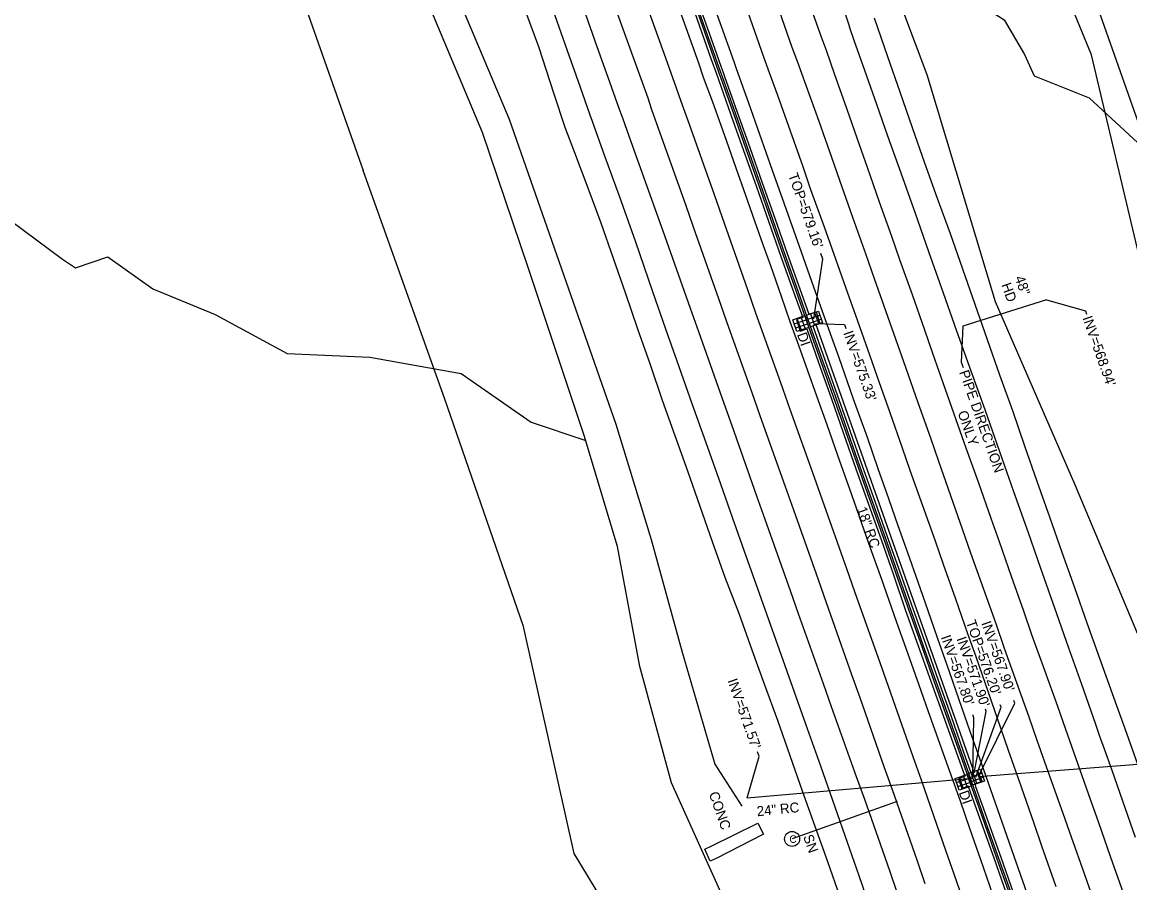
# Model space of a CAD drawing. Extents: x 2004847 to 2009016, y 1134161 to 1140101.
# Drawn here: x 2005737 to 2006180, y 1136539.1 to 1136883.1 of the extents above; entities that cross this region are included whole.
import ezdxf

# ---------------------------------------------------------------- set-up
doc = ezdxf.new("R2010")
doc.units = 0
for name, color, linetype in [('RD_EX_BldgApp', 7, 'Continuous'), ('RD_EX_Conc', 7, 'Continuous'), ('RD_EX_DR_Inlet', 7, 'Continuous'), ('RD_EX_DR_Inlet_txCode', 7, 'Continuous'), ('RD_EX_DR_Pipe', 7, 'Continuous'), ('RD_EX_DR_Pipe_txCode', 7, 'Continuous'), ('RD_EX_Fence_Other', 7, 'Continuous'), ('RD_EX_H2O', 7, 'Continuous'), ('RD_EX_Pavement_Markings', 7, 'Continuous'), ('RD_EX_Road', 7, 'Continuous'), ('RD_EX_VEG', 7, 'Continuous'), ('RD_Sketch3', 7, 'Continuous')]:
    doc.layers.add(name, color=color, linetype=linetype)

msp = doc.modelspace()

# ---------------------------------------------------------------- linework, layer by layer
at = {"layer": 'RD_EX_BldgApp'}
msp.add_line((2006086.98, 1136571.69), (2006044.94, 1136556.66), dxfattribs=at)
msp.add_circle((2006044.94, 1136556.66), 3, dxfattribs=at)
at = {"layer": 'RD_EX_Conc'}
for points in [[(2006007.3, 1136886.49), (2006013.51, 1136868.96), (2006015.67, 1136862.89)], [(2006007.95, 1136886.72), (2006014.16, 1136869.19), (2006016.34, 1136863.12)], [(2006016.34, 1136863.12), (2006017.1, 1136860.99), (2006022.11, 1136846.82), (2006027.09, 1136832.69), (2006032.1, 1136818.53), (2006037.11, 1136804.4), (2006042.08, 1136790.23), (2006047.09, 1136776.11), (2006052.06, 1136761.96), (2006057.08, 1136747.79), (2006062.1, 1136733.72), (2006067.06, 1136719.52), (2006072.04, 1136705.43), (2006077.05, 1136691.29), (2006082.11, 1136677.12), (2006087.08, 1136662.99), (2006092.42, 1136647.93), (2006097.41, 1136633.78), (2006102.42, 1136619.66), (2006107.44, 1136605.55), (2006112.48, 1136591.38), (2006117.46, 1136577.26), (2006122.46, 1136563.12), (2006127.45, 1136548.98), (2006132.48, 1136534.83)], [(2006015.67, 1136862.89), (2006016.43, 1136860.75), (2006021.44, 1136846.58), (2006026.43, 1136832.46), (2006031.43, 1136818.29), (2006036.44, 1136804.17), (2006041.41, 1136789.99), (2006046.41, 1136775.87), (2006051.4, 1136761.73), (2006056.38, 1136747.54), (2006061.42, 1136733.48), (2006066.42, 1136719.29), (2006071.36, 1136705.2), (2006076.37, 1136691.05), (2006081.43, 1136676.88), (2006086.42, 1136662.75), (2006091.78, 1136647.71), (2006096.77, 1136633.55), (2006101.75, 1136619.43), (2006106.78, 1136605.32), (2006111.84, 1136591.15), (2006116.8, 1136577.03), (2006121.82, 1136562.9), (2006126.82, 1136548.76), (2006131.84, 1136534.6)], [(2006031.24, 1136563.01), (2006033.54, 1136558.63), (2006014.52, 1136548.85), (2006012.21, 1136547.76), (2006010, 1136552.54), (2006012.88, 1136553.92), (2006031.24, 1136563.01)]]:
    msp.add_lwpolyline(points, dxfattribs=at)
at = {"layer": 'RD_EX_DR_Inlet'}
for p, q in [((2006051.27, 1136764.4), (2006056, 1136766.02)), ((2006052.33, 1136766.56), (2006053.95, 1136761.83)), ((2006053.94, 1136767.11), (2006055.56, 1136762.38)), ((2006045.82, 1136762.58), (2006050.55, 1136764.2)), ((2006046.38, 1136760.97), (2006051.1, 1136762.59)), ((2006046.88, 1136764.74), (2006048.5, 1136760.01)), ((2006048.49, 1136765.29), (2006050.11, 1136760.56)), ((2006051.83, 1136762.79), (2006056.56, 1136764.41)), ((2006118.74, 1136583.99), (2006120.36, 1136579.26)), ((2006110.68, 1136579.25), (2006115.41, 1136580.87)), ((2006111.74, 1136581.41), (2006113.36, 1136576.68)), ((2006113.35, 1136581.96), (2006114.97, 1136577.23)), ((2006116.07, 1136581.28), (2006120.8, 1136582.9)), ((2006116.62, 1136579.67), (2006121.35, 1136581.29)), ((2006117.13, 1136583.44), (2006118.75, 1136578.71)), ((2006111.24, 1136577.64), (2006115.97, 1136579.27))]:
    msp.add_line(p, q, dxfattribs=at)
for points in [[(2006046.89, 1136759.46), (2006045.27, 1136764.19), (2006050, 1136765.81), (2006051.62, 1136761.08)], [(2006052.35, 1136761.28), (2006050.72, 1136766.01), (2006055.45, 1136767.63), (2006057.07, 1136762.9)], [(2006117.14, 1136578.16), (2006115.52, 1136582.89), (2006120.25, 1136584.51), (2006121.87, 1136579.78)], [(2006111.76, 1136576.13), (2006110.13, 1136580.86), (2006114.86, 1136582.48), (2006116.48, 1136577.75)]]:
    msp.add_lwpolyline(points, close=True, dxfattribs=at)
at = {"layer": 'RD_EX_DR_Inlet_txCode'}
for points in [[(2006053.68, 1136764.51), (2006057.21, 1136788.45), (2006056.43, 1136790.65)], [(2006146.61, 1136772.12), (2006162.25, 1136767.77), (2006162.73, 1136766.42)], [(2006054.34, 1136762.66), (2006065.84, 1136762.23), (2006066.38, 1136760.72)], [(2006113.27, 1136761.61), (2006112.59, 1136747.24), (2006113.35, 1136745.07)], [(2006119.44, 1136581.64), (2006133.98, 1136610.91), (2006133.59, 1136611.99)], [(2006117.22, 1136580.93), (2006117.65, 1136605.07), (2006117.22, 1136606.27)], [(2006117.68, 1136583.02), (2006122.6, 1136607.63), (2006122.26, 1136608.59)], [(2006118.38, 1136581.29), (2006128.51, 1136609.38), (2006128.17, 1136610.32)], [(2006027.02, 1136573.08), (2006031.74, 1136589.67), (2006031.08, 1136591.52)]]:
    msp.add_lwpolyline(points, dxfattribs=at)
at = {"layer": 'RD_EX_DR_Pipe'}
for p, q in [((2006146.61, 1136772.12), (2006113.27, 1136761.61)), ((2006054.34, 1136762.66), (2006117.68, 1136583.02)), ((2006119.44, 1136581.64), (2006216.19, 1136589.1)), ((2006027.02, 1136573.08), (2006117.22, 1136580.93))]:
    msp.add_line(p, q, dxfattribs=at)
at = {"layer": 'RD_EX_Fence_Other'}
for points in [[(2006288.09, 1136544.58), (2006263.66, 1136615.63), (2006139.34, 1136967.96), (2006112.64, 1137043.07), (2006085.14, 1137118.91), (2006043.88, 1137235.25)], [(2005728.21, 1137230.79), (2005760.44, 1137139.08), (2005796.83, 1137035.67), (2005834.26, 1136935.09), (2005873.43, 1136823.78)], [(2006150.07, 1136043.34), (2006115.42, 1136139.93), (2006088.15, 1136218.09), (2006055.25, 1136311.48), (2006039.49, 1136357.1), (2006011.97, 1136432.75), (2005987.61, 1136501.5), (2005957.81, 1136550.91), (2005937.54, 1136641.63), (2005905.9, 1136732.88), (2005873.43, 1136823.78)]]:
    msp.add_lwpolyline(points, dxfattribs=at)
at = {"layer": 'RD_EX_H2O'}
msp.add_line((2005890.91, 1136941.31), (2005931.83, 1136844.29), dxfattribs=at)
for points in [[(2006112.75, 1136895.16), (2006129.71, 1136884.09), (2006137.9, 1136870.17), (2006141.69, 1136861.69), (2006163.76, 1136852.86), (2006190.28, 1136828.31), (2006196.59, 1136825.58), (2006201.05, 1136821.34), (2006205.27, 1136803.37), (2006204.48, 1136793.17), (2006204.25, 1136788.49), (2006204.86, 1136785.27), (2006219.54, 1136760.55), (2006230.66, 1136720.9)], [(2005601.87, 1136857.12), (2005648.58, 1136838.79), (2005694.69, 1136815.74), (2005732.31, 1136803.89), (2005753.19, 1136788.44), (2005758.39, 1136784.92), (2005771.25, 1136789.37), (2005789.24, 1136776.48), (2005814.15, 1136766.21), (2005843, 1136750.65), (2005876.07, 1136749.26)], [(2005931.83, 1136844.29), (2005974.38, 1136722.42), (2005988.63, 1136676.28), (2006001.03, 1136631.25), (2006014.08, 1136586.56), (2006024.85, 1136569.76)], [(2005876.07, 1136749.26), (2005912.53, 1136742.74), (2005940.55, 1136723.3), (2005962.09, 1136716.06)]]:
    msp.add_lwpolyline(points, dxfattribs=at)
at = {"layer": 'RD_EX_Pavement_Markings'}
for points in [[(2005835.74, 1137463.95), (2005849.99, 1137423.41), (2005864.31, 1137382.86), (2005875.05, 1137352.62), (2005889.45, 1137312.13), (2005903.79, 1137271.58), (2005914.78, 1137240.52), (2005929.22, 1137200.01), (2005943.64, 1137159.42), (2005954.6, 1137128.67), (2005968.92, 1137088.12), (2005983.37, 1137047.61), (2005994.06, 1137017.35), (2006008.29, 1136976.82), (2006022.62, 1136936.24), (2006033.58, 1136905.38), (2006044.8, 1136873.16)], [(2005848.16, 1137465.29), (2005862.54, 1137424.75), (2005873.26, 1137394.52), (2005887.52, 1137353.9), (2005901.86, 1137313.37), (2005912.8, 1137282.58), (2005927.2, 1137242.01), (2005941.56, 1137201.48), (2005952.55, 1137170.5), (2005966.97, 1137129.93), (2005981.38, 1137089.36), (2005992.2, 1137058.91), (2006006.54, 1137018.29), (2006020.9, 1136977.7), (2006031.81, 1136946.87), (2006046.21, 1136906.41), (2006056.57, 1136877.31)], [(2005825.14, 1137456.53), (2005839.37, 1137416.27), (2005850.1, 1137385.98), (2005864.5, 1137345.52), (2005878.93, 1137305.04), (2005893.4, 1137264.58), (2005904.08, 1137234.38), (2005918.39, 1137193.9), (2005932.63, 1137153.59), (2005943.36, 1137123.21), (2005957.73, 1137082.68), (2005972.14, 1137042.14), (2005982.82, 1137011.92), (2005997.23, 1136971.41), (2006011.61, 1136930.93), (2006022.67, 1136900.11), (2006033.56, 1136869.2)], [(2005788.73, 1137449.51), (2005803, 1137409.01), (2005817.4, 1137368.41), (2005828.16, 1137338.06), (2005842.73, 1137297.51), (2005857.07, 1137256.98), (2005871.02, 1137217), (2005881.73, 1137186.76), (2005896.21, 1137146.35), (2005910.61, 1137105.91), (2005921.22, 1137075.91), (2005935.53, 1137035.34), (2005949.65, 1136994.87), (2005963.61, 1136954.72), (2005974.36, 1136924.56), (2005988.85, 1136884.03), (2005994.3, 1136868.9), (2005998.63, 1136856.88)], [(2005778, 1137442.79), (2005792.39, 1137402.39), (2005803.4, 1137371.72), (2005817.89, 1137331.26), (2005832.25, 1137290.71), (2005846.44, 1137250.45), (2005857.1, 1137220.18), (2005871.38, 1137179.56), (2005885.58, 1137139.16), (2005896.39, 1137108.89), (2005910.75, 1137068.36), (2005925.12, 1137028.01), (2005939.05, 1136988.07), (2005949.65, 1136958.07), (2005963.92, 1136917.61), (2005978.44, 1136877.06), (2005982.82, 1136864.95), (2005987.2, 1136852.84)], [(2005766.92, 1137438.17), (2005781.39, 1137397.9), (2005805.91, 1137329.14), (2005820.24, 1137288.64), (2005834.58, 1137248.13), (2005845.47, 1137217.44), (2005859.69, 1137176.75), (2005873.98, 1137136.26), (2005888.4, 1137095.83), (2005898.99, 1137065.59), (2005913.39, 1137025.13), (2005927.49, 1136984.67), (2005938.3, 1136954.56), (2005952.56, 1136914.1), (2005966.89, 1136873.36), (2005971.3, 1136861.07), (2005975.7, 1136848.79)], [(2005997.41, 1136895.07), (2006002.48, 1136880.99), (2006007.46, 1136866.83), (2006009.42, 1136861.19)], [(2006011.51, 1136895.68), (2006016.59, 1136881.5), (2006021.64, 1136867.42), (2006022.49, 1136865.05)], [(2005949.93, 1136886.14), (2005955.01, 1136871.74), (2005960.01, 1136857.47), (2005964.1, 1136846.06)], [(2006066.22, 1136886.08), (2006067.85, 1136881.29)], [(2006182.24, 1136557.26), (2006177.23, 1136571.8), (2006172.89, 1136584.01), (2006169.86, 1136592.56), (2006167.88, 1136598.05), (2006166.21, 1136602.83), (2006160.74, 1136618.39), (2006155.49, 1136633.27), (2006149.94, 1136648.95), (2006144.22, 1136665.2), (2006139.41, 1136678.97), (2006133.63, 1136695.43), (2006127.94, 1136711.45), (2006122.09, 1136728.21), (2006116.54, 1136743.66), (2006110.82, 1136759.64), (2006105.47, 1136774.82), (2006099.62, 1136791.31), (2006094.24, 1136806.59), (2006088.52, 1136822.82), (2006083.27, 1136837.56), (2006078.83, 1136850.21), (2006073.99, 1136863.81), (2006069.79, 1136875.82), (2006067.85, 1136881.29)], [(2006056.57, 1136877.31), (2006058.49, 1136871.88), (2006061.8, 1136862.53), (2006066.78, 1136848.4), (2006071.76, 1136834.27), (2006074.92, 1136825.1), (2006079.8, 1136811.32), (2006084.68, 1136797.55), (2006087.93, 1136788.28), (2006092.91, 1136774.23), (2006097.89, 1136760.19), (2006101.1, 1136750.87), (2006106.17, 1136736.48), (2006111.24, 1136722.1), (2006114.45, 1136713), (2006119.41, 1136698.95), (2006124.38, 1136684.91), (2006127.7, 1136675.55), (2006132.58, 1136661.68), (2006137.45, 1136647.81), (2006140.72, 1136638.41), (2006145.86, 1136624.06), (2006151.01, 1136609.72), (2006154.2, 1136600.56), (2006159.19, 1136586.56), (2006164.18, 1136572.56), (2006167.3, 1136563.62), (2006172.29, 1136549.4), (2006177.28, 1136535.18)], [(2006044.8, 1136873.16), (2006047.01, 1136867.47), (2006050.44, 1136857.88), (2006055.57, 1136843.53), (2006060.7, 1136829.17), (2006063.86, 1136819.99), (2006069.13, 1136805.12), (2006074.4, 1136790.25), (2006077.73, 1136780.72), (2006082.38, 1136767.48), (2006087.02, 1136754.24), (2006090.25, 1136745.19), (2006095.25, 1136731.11), (2006100.26, 1136717.02), (2006103.44, 1136707.64), (2006108.22, 1136693.96), (2006113.01, 1136680.27), (2006116.31, 1136671), (2006121.33, 1136656.88), (2006126.34, 1136642.76), (2006129.74, 1136632.93), (2006134.65, 1136619.2), (2006139.57, 1136605.47), (2006142.83, 1136596.15), (2006148.03, 1136581.54), (2006153.23, 1136566.92), (2006156.54, 1136557.48), (2006161.69, 1136542.91), (2006166.84, 1136528.35)], [(2006033.56, 1136869.2), (2006035.81, 1136863.06), (2006039.05, 1136853.95), (2006044.14, 1136839.67), (2006049.22, 1136825.4), (2006052.35, 1136816.28), (2006057.71, 1136801.3), (2006063.08, 1136786.32), (2006066.23, 1136777.25), (2006071.08, 1136763.7), (2006075.92, 1136750.14), (2006078.96, 1136741.35), (2006083.97, 1136727.16), (2006088.98, 1136712.98), (2006092.08, 1136704.09), (2006097.11, 1136689.92), (2006102.15, 1136675.76), (2006105.34, 1136666.43), (2006110.24, 1136652.61), (2006115.14, 1136638.79), (2006118.37, 1136629.57), (2006123.31, 1136615.32), (2006128.25, 1136601.07), (2006131.39, 1136592.11), (2006136.5, 1136577.55), (2006141.6, 1136562.99), (2006144.73, 1136553.93), (2006150.43, 1136537.67)], [(2006022.49, 1136865.05), (2006024.62, 1136858.95), (2006027.48, 1136850.9), (2006031.92, 1136838.31), (2006036.96, 1136823.94), (2006041.74, 1136810.48), (2006047.73, 1136793.59), (2006052.74, 1136779.55), (2006058.26, 1136763.93), (2006063.6, 1136749.13), (2006069.39, 1136732.63), (2006074.91, 1136717.19), (2006079.25, 1136704.67), (2006083.42, 1136692.72), (2006087.22, 1136681.88), (2006091.02, 1136671.21), (2006095.19, 1136659.43), (2006099.19, 1136647.99), (2006102.99, 1136637.15), (2006107.77, 1136623.56), (2006111.67, 1136612.35), (2006116.01, 1136599.76), (2006120.62, 1136586.67), (2006122.47, 1136581.81), (2006134.46, 1136547.45), (2006172.52, 1136438.91)], [(2006009.42, 1136861.19), (2006013.06, 1136851.26), (2006016.39, 1136841.9), (2006019.48, 1136833.22), (2006022.44, 1136824.84), (2006026.24, 1136814.03), (2006029.91, 1136803.67), (2006033.24, 1136794.31), (2006036.3, 1136785.8), (2006040.54, 1136773.61), (2006044.07, 1136763.52), (2006047.47, 1136753.99), (2006051.1, 1136743.86), (2006054.73, 1136733.76), (2006058.84, 1136722.32), (2006063.14, 1136710.07), (2006068.66, 1136694.32), (2006072.73, 1136682.81), (2006076.16, 1136672.98), (2006080.63, 1136660.46), (2006086.69, 1136643.3), (2006090.42, 1136632.93), (2006095.67, 1136618.26), (2006099.27, 1136607.96), (2006102.02, 1136600.12), (2006107.84, 1136583.72), (2006112.08, 1136571.84), (2006115.92, 1136561.01), (2006120.32, 1136548.39), (2006125.13, 1136534.55)], [(2005998.63, 1136856.88), (2006000.46, 1136851.59), (2006003.81, 1136842.32), (2006013.77, 1136814.19), (2006016.83, 1136805.38), (2006027.14, 1136776.26), (2006030.36, 1136766.99), (2006040.28, 1136739.06), (2006044.04, 1136728.39), (2006053.72, 1136701.3), (2006057, 1136692.14), (2006066.72, 1136664.79), (2006069.94, 1136655.55), (2006080.07, 1136627.22), (2006083.38, 1136617.66), (2006093.24, 1136589.62), (2006096.49, 1136580.33), (2006106.43, 1136551.81), (2006109.64, 1136542.66), (2006119.64, 1136513.92)], [(2005987.2, 1136852.84), (2005988.73, 1136848.24), (2005992.09, 1136838.92), (2006002.32, 1136810.27), (2006005.39, 1136801.26), (2006015.51, 1136772.67), (2006018.64, 1136763.52), (2006028.81, 1136735.08), (2006032.04, 1136725.84), (2006042.13, 1136697.53), (2006045.43, 1136688.25), (2006055.31, 1136660.32), (2006058.52, 1136651.18), (2006068.72, 1136622.41), (2006071.98, 1136613.25), (2006081.68, 1136585.56), (2006084.94, 1136576.44), (2006094.82, 1136548.31), (2006098.06, 1136538.91)], [(2005964.1, 1136846.06), (2005965.01, 1136843.5), (2005969.92, 1136829.67), (2005975.74, 1136813.65), (2005982.27, 1136795.34), (2005989.16, 1136775.51), (2005994.31, 1136760.5), (2005999.62, 1136745.53), (2006004.87, 1136730.72), (2006010.42, 1136715.13), (2006016.27, 1136698.61), (2006021.12, 1136684.84), (2006027.04, 1136667.95), (2006032.59, 1136652.64), (2006038.27, 1136636.55), (2006044.29, 1136619.65), (2006050.31, 1136602.62), (2006056.3, 1136585.83), (2006061.98, 1136569.5), (2006066.89, 1136555.44), (2006071.6, 1136542.04), (2006076.82, 1136527)], [(2005975.7, 1136848.79), (2005977.22, 1136844.53), (2005980.45, 1136835.47), (2005990.77, 1136806.83), (2005993.94, 1136797.79), (2006004.21, 1136768.76), (2006007.54, 1136759.44), (2006017.59, 1136730.89), (2006020.78, 1136721.87), (2006030.72, 1136693.83), (2006033.98, 1136684.51), (2006044.13, 1136655.98), (2006047.34, 1136646.83), (2006057.39, 1136618.76), (2006060.6, 1136609.64), (2006070.6, 1136581.65), (2006073.83, 1136572.58), (2006083.86, 1136543.99), (2006087.01, 1136534.95)]]:
    msp.add_lwpolyline(points, dxfattribs=at)
at = {"layer": 'RD_EX_Road'}
msp.add_line((2006119.11, 1136584.03), (2006116.4, 1136583.13), dxfattribs=at)
for points in [[(2006005.79, 1136895.69), (2006012.46, 1136876.83), (2006016.44, 1136865.55), (2006017.19, 1136863.42)], [(2005936.53, 1136892.13), (2005943.57, 1136873.44), (2005949.66, 1136854.41), (2005954.01, 1136841.14)], [(2006006.02, 1136886.82), (2006012.49, 1136868.6), (2006014.64, 1136862.52)], [(2006077.77, 1136884.79), (2006083.11, 1136869.35), (2006088.07, 1136855.26), (2006092.9, 1136841), (2006097.92, 1136826.92), (2006102.9, 1136812.74), (2006108.08, 1136798.66), (2006113.07, 1136784.54), (2006117.99, 1136770.34), (2006123, 1136756.26), (2006127.9, 1136742.1), (2006133.02, 1136727.91), (2006137.89, 1136713.78), (2006142.85, 1136699.62), (2006147.81, 1136685.44), (2006152.82, 1136671.28), (2006157.87, 1136657.18), (2006162.79, 1136643.03), (2006167.86, 1136628.9), (2006172.94, 1136614.78), (2006177.98, 1136600.74), (2006183.04, 1136586.57)], [(2006017.19, 1136863.42), (2006017.94, 1136861.35), (2006022.94, 1136847.2), (2006027.97, 1136833.07), (2006033, 1136818.93), (2006038.02, 1136804.79), (2006043, 1136790.63), (2006048.02, 1136776.52), (2006051.56, 1136766.4)], [(2006014.64, 1136862.52), (2006015.46, 1136860.2), (2006020.48, 1136846.02), (2006025.47, 1136831.86), (2006030.54, 1136817.74), (2006035.55, 1136803.62), (2006040.48, 1136789.48), (2006045.48, 1136775.29), (2006049.16, 1136765.14)], [(2005954.01, 1136841.14), (2005957.93, 1136831.05), (2005963.21, 1136816.92), (2005968.38, 1136802.91), (2005973.34, 1136788.84), (2005978.27, 1136774.68), (2005983.04, 1136760.51), (2005988.2, 1136746.3), (2005993, 1136732.1), (2005998.07, 1136717.96), (2006003.04, 1136703.83), (2006008.03, 1136689.71), (2006012.97, 1136675.56), (2006018, 1136661.31), (2006023.77, 1136646.48), (2006028.77, 1136632.31), (2006033.96, 1136618.23), (2006039.15, 1136604.19), (2006044.08, 1136590), (2006048.91, 1136575.88), (2006054.06, 1136561.77), (2006059.15, 1136547.64), (2006063.98, 1136533.49)], [(2006051.56, 1136766.4), (2006054.5, 1136767.38), (2006056.08, 1136762.73), (2006053.19, 1136761.76)], [(2006049.16, 1136765.14), (2006046.64, 1136764.24), (2006048.16, 1136759.63), (2006050.82, 1136760.48)], [(2006053.19, 1136761.76), (2006058.01, 1136748.19), (2006063.02, 1136734.11), (2006068, 1136719.93), (2006072.96, 1136705.84), (2006077.96, 1136691.68), (2006082.99, 1136677.51), (2006088, 1136663.39), (2006093.34, 1136648.33), (2006098.37, 1136634.19), (2006103.35, 1136620.06), (2006108.37, 1136605.94), (2006113.36, 1136591.77), (2006116.4, 1136583.13), (2006117.95, 1136578.72)], [(2006050.82, 1136760.48), (2006055.53, 1136747.07), (2006060.52, 1136732.93), (2006065.53, 1136718.76), (2006070.47, 1136704.59), (2006075.48, 1136690.47), (2006080.49, 1136676.31), (2006085.49, 1136662.21), (2006090.29, 1136647.97), (2006095.38, 1136633.89), (2006100.47, 1136619.74), (2006105.51, 1136605.63), (2006110.55, 1136591.52), (2006114.03, 1136581.75)], [(2006117.95, 1136578.72), (2006120.88, 1136579.74), (2006119.11, 1136584.03)], [(2006114.03, 1136581.75), (2006111.46, 1136580.71), (2006112.83, 1136576.81), (2006115.39, 1136577.85)], [(2006115.39, 1136577.85), (2006115.54, 1136577.38), (2006120.52, 1136563.22), (2006125.58, 1136549.07), (2006130.6, 1136534.99), (2006135.61, 1136520.77), (2006140.62, 1136506.67), (2006145.63, 1136492.55), (2006150.53, 1136478.4), (2006155.62, 1136464.29), (2006160.66, 1136450.15), (2006165.63, 1136436.02), (2006170.61, 1136421.87), (2006170.87, 1136421.15)], [(2006117.95, 1136578.72), (2006118.33, 1136577.63), (2006123.3, 1136563.48), (2006128.35, 1136549.35), (2006133.36, 1136535.21), (2006138.37, 1136521.07), (2006143.36, 1136506.93), (2006148.41, 1136492.81), (2006153.45, 1136478.68), (2006158.59, 1136464.59), (2006163.42, 1136450.39), (2006168.46, 1136436.23), (2006173.24, 1136422.52)]]:
    msp.add_lwpolyline(points, dxfattribs=at)
at = {"layer": 'RD_EX_VEG'}
for points in [[(2006280.68, 1136541.58), (2006256.14, 1136612.63), (2006212.27, 1136710.57), (2006184.24, 1136787.39), (2006164.61, 1136870.02), (2006126.52, 1136962.8), (2006100.79, 1137039.92), (2006066.88, 1137123.34), (2006027.09, 1137230.77), (2006008.37, 1137303.96), (2005999.5, 1137331.93)], [(2005921.12, 1136839.02), (2005879.84, 1136937.44), (2005840.96, 1137039.96), (2005810.28, 1137148.31), (2005779.11, 1137247.96)], [(2006061.81, 1137035.33), (2006055.47, 1136986.65), (2006066.5, 1136947.96), (2006098.85, 1136862.24), (2006126.13, 1136771.44), (2006157.91, 1136698.56), (2006202.97, 1136591.32), (2006221.46, 1136521.07)], [(2005961.75, 1136717.89), (2005939.41, 1136785.12), (2005921.12, 1136839.02)], [(2006039.1, 1136535.19), (2006016.14, 1136535.95), (2005996.66, 1136579.1), (2005983.98, 1136625.63), (2005975.17, 1136673.57), (2005961.75, 1136717.89)]]:
    msp.add_lwpolyline(points, dxfattribs=at)

# ---------------------------------------------------------------- texts
at = {"layer": 'RD_EX_BldgApp'}
msp.add_text('C', height=3, dxfattribs=at).set_placement((2006043.86, 1136555.1))
at = {"layer": 'RD_EX_DR_Inlet_txCode'}
for s, p in [("TOP=579.16'", (2006043.29, 1136822.04)), ("INV=568.94'", (2006160.98, 1136764.89)), ('DI', (2006046.84, 1136758.31)), ("INV=575.33'", (2006065.34, 1136758.95)), ('PIPE DIRECTION', (2006111.71, 1136743.25)), ('ONLY', (2006111.07, 1136727.05)), ("TOP=576.20'", (2006114.41, 1136643.39)), ("INV=567.90'", (2006120.51, 1136642.92)), ("INV=567.80'", (2006104.37, 1136637.33)), ("INV=571.90'", (2006110.63, 1136636.69)), ("INV=571.57'", (2006019.06, 1136619.96)), ('DI', (2006111.55, 1136575.21))]:
    msp.add_text(s, height=4, rotation=289.4494, dxfattribs=at).set_placement(p)
at = {"layer": 'RD_EX_DR_Pipe_txCode'}
for s, rotation, p in [('HD', 289.4494, (2006128.54, 1136778.14)), ('48"', 289.4494, (2006133.91, 1136780.97)), ('18" RC', 289.4494, (2006070.77, 1136688.59)), ('24" RC', 5.7387, (2006030.99, 1136565.7))]:
    msp.add_text(s, height=4, rotation=rotation, dxfattribs=at).set_placement(p)
at = {"layer": 'RD_Sketch3'}
for s, p in [('CONC', (2006011.55, 1136574.77)), ('SN', (2006049.29, 1136557.65))]:
    msp.add_text(s, height=4, rotation=289.4494, dxfattribs=at).set_placement(p)

doc.saveas('drawing.dxf')
